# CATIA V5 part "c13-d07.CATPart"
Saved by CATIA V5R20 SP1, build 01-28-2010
Part number: Part1
Bounding box of the stored display mesh (mm): x -49.812 to 35, y -44.222 to 44.222, z 0 to 30
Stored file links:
  D:\v5_r20\psrt_files_downloaded\c13-catia-v5r20-prt\Tutorial-1\c13-d07.CATPart
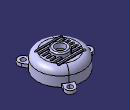
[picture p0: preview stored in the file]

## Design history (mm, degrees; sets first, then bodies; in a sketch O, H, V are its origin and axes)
Body1 (main body)
  Sketch1 on yz-plane, origin (0, 0, 0), H (0, 1, 0), V (0, 0, 1)
    line L1 (0, 0) -> (35, 0)
    line L2 (35, 0) -> (35, 15)
    arc A1 centre (25, 15) radius 10 from (35, 15) to (25, 25) ccw
    line L3 (25, 25) -> (0, 25)
    point P5 (0, 25)
    line L4 (0, 25) -> (0, 0)
    axis line L5 (0, 70.1891) -> (0, -36.6898)
    point P6 (0, 70.1891)
    "Radius" L2 L5 = 35
    distance L1 L3 = 25
    radius A1 = 10
    horizontal: L1 H
    vertical: L2 V, L4 V, L5 V
    tangency: A1 L2, L3 A1
    coincidence: P5 V, P6 V
  Shaft1: profile Sketch1, axis Sketch1.L5, angle 360
  Shell1: IntOffset 2.5, Face face of Shaft1, ExtOffset 0
  Sketch2 on face of Shaft1, origin (0, 0, 0), H (1, 0, 0), V (0, -1, 0)
    projected circle E1 centre (0, 0) radius 35 from edge [face of Shaft1 | face of Shaft1]
    projected arc E2 centre (0, 0) radius 35 from (-34.187, 7.5) to (-34.187, -7.5) ccw from edge [face of Shaft1 | face of Shaft1]
    point P1 (-34.187, 7.5)
    line L1 (-34.187, 7.5) -> (-42.5, 7.5)
    arc A1 centre (-42.5, 0) radius 7.5 from (-42.5, 7.5) to (-42.5, -7.5) ccw
    point P3 (-42.5, 0)
    line L2 (-42.5, -7.5) -> (-34.187, -7.5)
    point P5 (-34.187, -7.5)
    circle A2 centre (-42.5, 0) radius 3.75
    distance P3 V = 42.5
    radius A1 = 7.5
    radius A2 = 3.75
    coincidence: P1 E1, P5 E1, P3 H
    horizontal: L1 H, L2 H
    tangency: A1 L1, L2 A1
  Pad1: profile Sketch2, direction (0, 0, 1), length 5
  CircPattern1: of Pad1, instances 3, angular step 120 {= 360.0*1 deg/CircPattern1.AngularNumber}, axis from face of Shaft1
  Sketch3 on face of Shaft1, origin (0, 0, 25), H (1, 0, 0), V (0, 1, 0)
    construction line L1 (-20, -18) -> (20, -18)
    point P2 (20, -18)
    line L2 (-20, -16.25) -> (20, -16.25)
    line L3 (20, -19.75) -> (-20, -19.75)
    arc A1 centre (20, -18) radius 1.75 from (20, -16.25) to (20, -19.75) cw
    arc A2 centre (-20, -18) radius 1.75 from (-20, -19.75) to (-20, -16.25) cw
    length L1 = 40
    distance H L1 = 18
    distance P2 V = 20
    distance L3 L2 = 3.5
    horizontal: L1 H
    tangency: A1 L2, A2 L2, A1 L3, A2 L3
    parallelism: L1 L2
  Pocket1: profile Sketch3, direction (0, 0, -1), through (limit type 3)
  RectPattern1: of Pocket1, direction 1 instances 7, spacing 6, along yz-plane
  Sketch4 on yz-plane, origin (0, 0, 0), H (0, 1, 0), V (0, 0, 1)
    axis line L1 (0, 0) -> (0, 35.5018)
    point P2 (0, 22.5)
    line L2 (0, 22.5) -> (12.5, 22.5)
    line L3 (12.5, 22.5) -> (12.5, 28)
    arc A1 centre (10.5, 28) radius 2 from (12.5, 28) to (10.5, 30) ccw
    line L4 (10.5, 30) -> (0, 30)
    point P7 (0, 30)
    line L5 (0, 30) -> (0, 22.5)
    reference intersected line E1 (25, 22.5) -> (-25, 22.5) from face of Shell1
    "Radius" L3 L1 = 12.5
    distance L4 L2 = 7.5
    radius A1 = 2
    vertical: L1 V, L3 V, L5 V
    coincidence: P2 L1, P7 L1, L2 E1
    horizontal: L2 H, L4 H
    tangency: A1 L3, L4 A1
  Shaft2: profile Sketch4, axis Sketch4.L1, angle 360
  Sketch5 on face of Shaft2, origin (0, 0, 30), H (1, 0, 0), V (0, 1, 0)
    point P1 (0, 0)
    reference projected circle E1 centre (0, 0) radius 12.5 from edge [face of Shaft2 | face of Shaft2]
    concentricity: P1 E1
  Hole1: placed by Sketch5, at (0, 0, 30) direction (0, 0, -1), diameter 15, through (limit type 3)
